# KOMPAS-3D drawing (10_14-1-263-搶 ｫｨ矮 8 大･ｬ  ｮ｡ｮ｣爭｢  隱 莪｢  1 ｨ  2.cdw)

Views: Вид 1, Вид 2
Referenced files in C:\Program Files\ASCON\KOMPAS-3D V9\Libs\: ELUSTR.LFR
Referenced files in C:\Program Files\ASCON\KOMPAS-3D V8 Plus\Libs\: ELUSTR.LFR
Referenced files: Блок выключателя QW1G.cdw
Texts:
  Текст на чертеже
  Размерные надписи
  Шероховатость
  Линия-выноска #1
  Линия-выноска #2
  Линия-выноска #3
  Отклонения формы и база
  Заголовок таблицы
  Ячейка таблицы
  Стрелка вида
  Обозначение изменения
  Фигурная скобка
  Номер узла
  Марка координационной оси
  VRCB
  Выносная надпись
  Обозначение узла
  Марка/позиционное обозначение с линией-выноской
  Марка/позиционное обозначение на линии
  Марка/позиционное обозначение без линии-выноски
  int C:\Program Files\ASCON\KOMPAS-3D V9\Libs\ELUSTR.LFR|Для меня|клемма1
  Для меня|клемма1
  int C:\Program Files\ASCON\KOMPAS-3D V8 Plus\Libs\ELUSTR.LFR|мои|Конт 1,5
  мои|Конт 1,5
  цепи
  Подпись в квадратике
  ссылки
  Без имени
  Additional DXF text style 0
  Лит-Масса-Масштаб
  Материал-Предприятие
  Обычный
  Термин
  Список определений
  Адрес
  Цитаты
  Форматированный
  Courier New
  Z-конец формы
  Z-начало формы
  Title Specification
  Body Specification ( left align )
  Body Specificaton ( centered )
  Simplex
  Txt
  Normal
  Body Text
  heading 1
  Знак Знак Знак Знак Знак Знак
  Verdana
  ТекстШаг1
  heading 8
  heading 3
  heading 6
  heading 7
  txt
  russ
  ООббыыччнныыйй
  ТТееррммиинн
  ССппииссоокк ооппррееддееллеенниийй
  ААддрреесс
  ЦЦииттааттыы
  ФФооррммааттиирроовваанннныыйй
  Z-ккооннеецц ффооррммыы
  Z-ннааччааллоо ффооррммыы
  Абзац Знак
  heading 2
  heading 4
  heading 5
  heading 9
  MS Sans Serif
  табл
  Тексты. 3,2
  ЗОНА_привяз
  Body Text 3
  Title
  Денис
  Клеммник текст
  текст переноса
  Маркировка
  клеммы, контакты
  тексты табл
  AGOpus
  footer
  маркировка
  текст табл
  подписи
  Аппараты
  Состав чартежа
  Body Text Indent 3
  Основной текст с отступом 3
  rustxt
  Table Contents
  Table Heading
  Tahoma
  Поз.
  GOST 2.304 type A
  Обозн.
  Кол.
  ЕК1, ЕК2
  KL1
  SA1
  XS1
  Обогреватель SK 3116.000, 50 Вт
  Термореле ТР-М01-1-15 220В
  Датчик температуры ТД-1-1-2
  Тумблер ТВ 1-2
  Розетка РАр10-3-ОП
  комплектно с ТР-М01-1-15
  Перечень  элементов
  ЕК1
  ЕК2
  Примечание - схему обогрева организовать в шкафах А1 и А2 клеммы 2 и 4 см. лист7
  POLYLINE_STYLE_0.40_RGB_0_0_0
  POLYLINE_STYLE_0.18_RGB_0_0_0
  CONTINUOUS0
  Реконструкция ПС 110 кВ Опорная
  (замена трансформаторов 16МВА на 40МВА)
  Н.контр.
  Схема обогрева шкафов собственных
  нужд реакторных
  Разраб.
  Cкахин
  Ведомость эскизного проекта
Dimensions and other numbers on the sheet: 10/14-1-263-ЭП; 7; 3,2 (надписи); 2,5 (контакты, клеммы); 2,5; 3,2_; 1,8; 2.5 курсив; 3.5; 2.5; 3,2_зона не привяз; 2,5_3; 2,5_01; 3,5_01; 2,3_; 5_заголовок; 3,5_tabl; 3,2; 2,5 грязносинь; 3,5; 5; 3,2 элементы; 3,2 линия; 3,2 таблица; 3.2 маркировка; 2.5_Э5_надписи; 2.5_Э5_ссылки; 2.5_кабель; 3.2; 2.5 надписи; 3,2 (Зоны); 3.2 (текст); 3.2 фиол; 2; 1; 4; 11; 14; 11.12; 0193.0-06-1-260-ЭП-; 8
